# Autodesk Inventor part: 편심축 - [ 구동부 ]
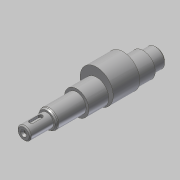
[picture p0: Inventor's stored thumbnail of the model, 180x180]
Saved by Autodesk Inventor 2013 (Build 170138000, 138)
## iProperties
Created: 2019-01
Part Number: 편심축 - [ 구동부 ]
Material: 강철, 연강
Document SubType Name: Modeling
Designer: mduedu
Density: 7.86 g/cm^3
Mass: 326.79 g
Surface Area: 90.982 cm^2
Volume: 41.5764 cm^3
Author: mduedu
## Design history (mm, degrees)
sketch "스케치1"
  geometry: L1 (0, 0)-(21, 0); L2 (21, 0)-(21, 6); L3 (21, 6)-(0, 6); L4 (0, 6)-(0, 0); L5 (21, 0)-(48, 0); L6 (48, 0)-(48, 8.5); L7 (48, 8.5)-(21, 8.5); L8 (21, 8.5)-(21, 0); L9 (48, 0)-(108, 0); L10 (108, 0)-(108, 11); L11 (108, 11)-(48, 11); L12 (48, 11)-(48, 0); L13 (108, 0)-(120, 0); L14 (120, 0)-(120, 8.5); L15 (120, 8.5)-(108, 8.5); L16 (108, 8.5)-(108, 0)
  constraints: 32 end point, 8 parallel, 4 horizontal, 4 perpendicular
  dimensions: "d0" = 120 distance between parallel lines of L14 L4; "d2" = 12 distance of L14.end L15.end; "d3" = 60 distance of L10.end L11.end; "d4" = 99 distance between parallel lines of L8 L14; "d5" = 12 diameter of L3 L1; "d6" = 17 diameter of L7 L5; "d7" = 17 diameter of L15 L13; "d8" = 22 diameter of L11 L9
revolve "회전1" sketch "스케치1" stored, may be unused: angle "d9" = 90 deg
node "작업 평면1"
sketch "스케치2"
  geometry: C1 r 15 at (0, 4); C2 r 11 at (0, 0) reference; 1 further point
  constraints: 1 centre point, 1 tangent, 1 vertical alignment
  dimensions: "d11" = 4 distance of point (0, 0) C1.centre
extrude "돌출1" join sketch "스케치2" distance "d12" = 24; taper "d13" = 0 deg
node "작업 평면2"
sketch "스케치3" dims "d16" = 12
  geometry: L1 (-4.5, 2)-(3.5, 2); L2 (3.5, 2)-(3.5, -2); L3 (3.5, -2)-(-4.5, -2); L4 (-4.5, -2)-(-4.5, 2); L5 (-10.5, 8.5)-(-10.5, -8.5) reference; 3 further points
  constraints: 8 end point, 2 midpoint, 2 parallel, 2 vertical alignment, 1 horizontal, 1 horizontal alignment, 1 perpendicular, 4 other
  dimensions: "d14" = 4 distance between parallel lines of L3 L1; "d17" = 4 dimension on L5
extrude "돌출2" cut sketch "스케치3" distance "d18" = 2.5; taper "d19" = 0 deg
chamfer "모따기1" distance "d20" = 1.82; stored, may be unused: second distance "d21" = 2, angle "d22" = 30 deg
fillet "모깎기1" dims "d23" = 2
hole "구멍2" diameter "d39" = 3.242; stored, may be unused: countersink angle "d43" = 60 deg, drill point angle "d45" = 118 deg; dims "d37" = 10, "d38" = 10, "d40" = 8, "d41" = 5.51, "d42" = 2, "d44" = 10
sketch "스케치5"
  geometry: L1 (0, 0)-(2, 0); L2 (2, 0)-(2, 1.621); L3 (0, 2.776)-(0, 0); L4 (0, 2.776)-(2, 1.621); L5 (10, 1.621)-(0, 1.621) reference
  constraints: 8 end point, 1 horizontal, 1 parallel, 1 perpendicular, 1 point on line
  dimensions: "d46" = 2 distance between parallel lines of L2 L3; "d48" = 30 deg angle of L4 L1
revolve "회전2" sketch "스케치5" stored, may be unused: angle "d50" = 90 deg
chamfer "모따기2" distance "d25" = 1; stored, may be unused: second distance "d26" = 2, angle "d27" = 30 deg
node "솔리드1"
